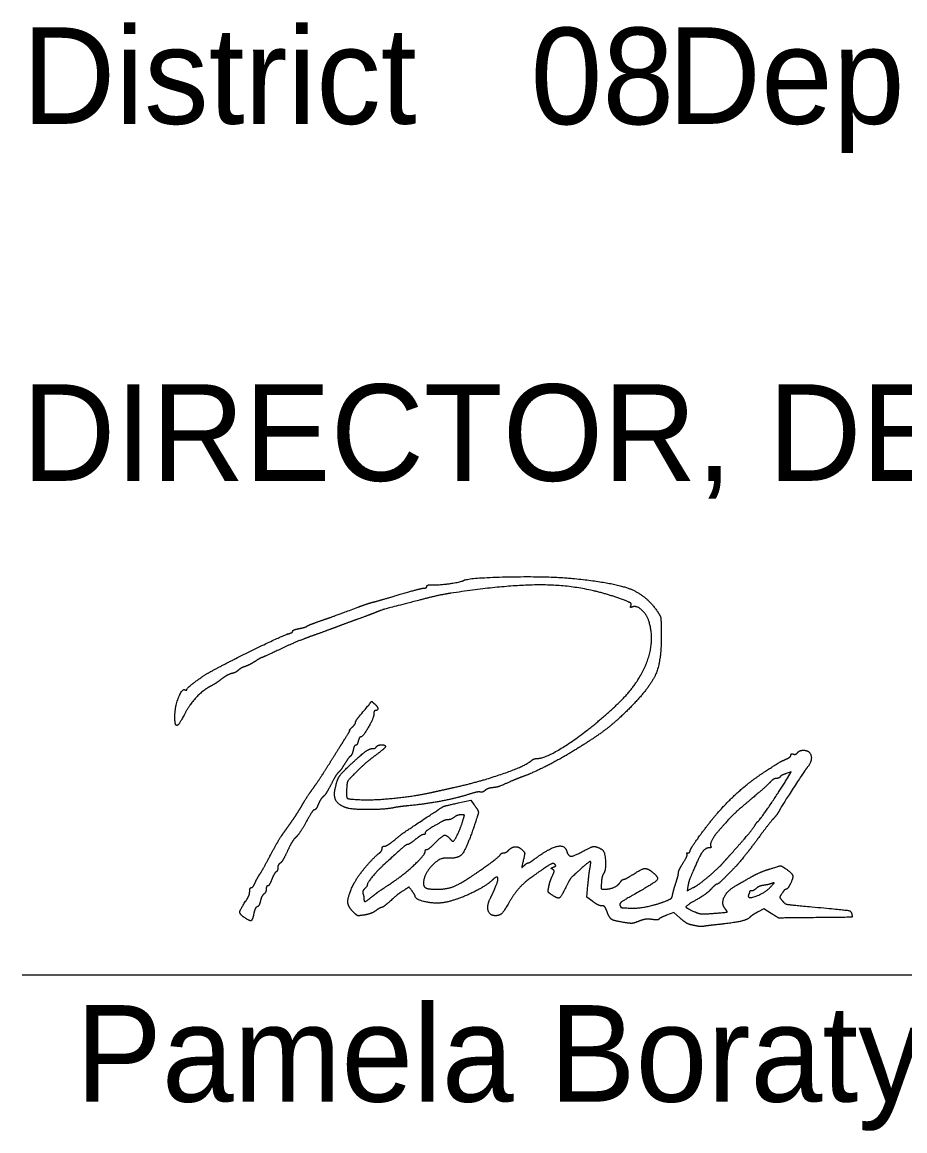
# Model space of a CAD drawing. Extents: x -7.5 to 26.5, y 3.5 to 25.5.
# Drawn here: x 17.043 to 18.323, y 10.747 to 12.355 of the extents above; entities that cross this region are included whole.
import ezdxf

# ---------------------------------------------------------------- set-up
doc = ezdxf.new("R2010")
doc.units = 0
doc.layers.add('SH_Data', color=7, linetype='Continuous')
doc.layers.add('SH_Text', color=7, linetype='Continuous')

msp = doc.modelspace()

# ---------------------------------------------------------------- linework, layer by layer
at = {"layer": 'SH_Data'}
msp.add_line((17.0432, 10.9729), (20.5432, 10.9729), dxfattribs=at)
at = {"layer": 'SH_Text'}
for points in [[(18.1528, 11.2584), (18.1582, 11.2674), (18.1508, 11.2648)], [(17.6755, 11.2223), (17.6935, 11.2263), (17.6981, 11.2201)], [(17.8704, 11.0795), (17.8621, 11.0858), (17.8635, 11.1029)], [(18.0084, 11.1014), (18.0074, 11.095), (18.016, 11.0994)], [(17.9974, 11.0551), (17.9882, 11.0634), (17.9776, 11.0593)], [(18.1292, 11.0621), (18.1186, 11.0689), (18.1102, 11.0644)]]:
    msp.add_lwpolyline(points, dxfattribs=at)
for points in [[(17.6389, 11.5386), (17.6484, 11.5383), (17.6794, 11.5427), (17.6829, 11.5448)], [(17.6829, 11.5448), (17.6896, 11.549), (17.8067, 11.5513), (17.8411, 11.5479)], [(17.8411, 11.5479), (17.9003, 11.5421), (17.9478, 11.5238), (17.9636, 11.5008)], [(17.5931, 11.5253), (17.6092, 11.53), (17.6241, 11.5339), (17.6261, 11.5339)], [(17.6261, 11.5339), (17.6282, 11.5339), (17.6299, 11.535), (17.6299, 11.5364)], [(17.6299, 11.5364), (17.6299, 11.5378), (17.6339, 11.5388), (17.6389, 11.5386)], [(17.9135, 11.5172), (17.863, 11.5362), (17.755, 11.5402), (17.6647, 11.5264)], [(17.5303, 11.5063), (17.5382, 11.5092), (17.549, 11.5128), (17.5543, 11.5141)], [(17.5543, 11.5141), (17.5595, 11.5155), (17.577, 11.5205), (17.5931, 11.5253)], [(17.6203, 11.5167), (17.5693, 11.5035), (17.565, 11.5023), (17.5543, 11.4979)], [(17.6647, 11.5264), (17.6554, 11.525), (17.6354, 11.5206), (17.6203, 11.5167)], [(17.9259, 11.5086), (17.9268, 11.5111), (17.9234, 11.5135), (17.9135, 11.5172)], [(17.4739, 11.4857), (17.4886, 11.4908), (17.495, 11.4931), (17.5303, 11.5063)], [(17.5543, 11.4979), (17.5516, 11.4968), (17.5414, 11.493), (17.5315, 11.4894)], [(17.9283, 11.5065), (17.9257, 11.5055), (17.9249, 11.5061), (17.9259, 11.5086)], [(17.9516, 11.4866), (17.9484, 11.4963), (17.9339, 11.5087), (17.9283, 11.5065)], [(17.9636, 11.5008), (17.9686, 11.4935), (17.9695, 11.4892), (17.9698, 11.4713)], [(17.4559, 11.4785), (17.4572, 11.4795), (17.4653, 11.4827), (17.4739, 11.4857)], [(17.5315, 11.4894), (17.5216, 11.4858), (17.5064, 11.4803), (17.4979, 11.477)], [(17.9061, 11.3654), (17.9371, 11.3948), (17.961, 11.4583), (17.9516, 11.4866)], [(17.3179, 11.4135), (17.3481, 11.4298), (17.4217, 11.4654), (17.4301, 11.4679)], [(17.4301, 11.4679), (17.433, 11.4687), (17.4355, 11.4703), (17.4355, 11.4714)], [(17.4355, 11.4714), (17.4355, 11.4725), (17.4395, 11.4741), (17.4445, 11.4751)], [(17.4445, 11.4751), (17.4494, 11.476), (17.4545, 11.4775), (17.4559, 11.4785)], [(17.4979, 11.477), (17.4893, 11.4738), (17.4731, 11.4679), (17.4619, 11.4639)], [(17.9698, 11.4713), (17.9706, 11.4305), (17.9545, 11.3908), (17.9251, 11.3609)], [(17.4619, 11.4639), (17.4506, 11.4599), (17.4303, 11.4514), (17.4166, 11.4449)], [(17.3908, 11.4331), (17.3902, 11.4331), (17.3857, 11.4306), (17.3808, 11.4275)], [(17.4166, 11.4449), (17.403, 11.4384), (17.3913, 11.4331), (17.3908, 11.4331)], [(17.366, 11.4199), (17.3627, 11.4189), (17.3586, 11.4166), (17.3568, 11.4148)], [(17.3808, 11.4275), (17.3759, 11.4244), (17.3692, 11.421), (17.366, 11.4199)], [(17.2819, 11.3869), (17.2819, 11.389), (17.3073, 11.4078), (17.3179, 11.4135)], [(17.3323, 11.4019), (17.3276, 11.3983), (17.3205, 11.3936), (17.3164, 11.3915)], [(17.3471, 11.41), (17.3436, 11.4091), (17.3369, 11.4055), (17.3323, 11.4019)], [(17.3568, 11.4148), (17.355, 11.413), (17.3506, 11.4108), (17.3471, 11.41)], [(17.2647, 11.349), (17.2648, 11.3622), (17.2754, 11.3888), (17.2796, 11.3862)], [(17.2796, 11.3862), (17.2808, 11.3855), (17.2819, 11.3858), (17.2819, 11.3869)], [(17.3164, 11.3915), (17.306, 11.3862), (17.2861, 11.3654), (17.2798, 11.3532)], [(17.5321, 11.348), (17.5506, 11.3701), (17.5499, 11.3695), (17.554, 11.3661)], [(17.2798, 11.3532), (17.2732, 11.3403), (17.2679, 11.3335), (17.2661, 11.3353)], [(17.5555, 11.3563), (17.5541, 11.3563), (17.5531, 11.354), (17.5531, 11.3512)], [(17.554, 11.3661), (17.5583, 11.3626), (17.5592, 11.3563), (17.5555, 11.3563)], [(17.7894, 11.2867), (17.8035, 11.2867), (17.8716, 11.3326), (17.9061, 11.3654)], [(17.9251, 11.3609), (17.9065, 11.342), (17.8741, 11.3171), (17.8436, 11.2983)], [(17.2661, 11.3353), (17.2653, 11.3361), (17.2646, 11.3423), (17.2647, 11.349)], [(17.5219, 11.3323), (17.5245, 11.3349), (17.5267, 11.3381), (17.5267, 11.3393)], [(17.5267, 11.3393), (17.5267, 11.3405), (17.5291, 11.3444), (17.5321, 11.348)], [(17.5531, 11.3512), (17.5531, 11.3457), (17.5371, 11.3179), (17.5339, 11.3179)], [(17.5091, 11.3118), (17.5146, 11.3205), (17.5187, 11.3275), (17.5181, 11.3275)], [(17.5181, 11.3275), (17.5175, 11.3275), (17.5192, 11.3297), (17.5219, 11.3323)], [(17.4871, 11.2768), (17.4937, 11.2875), (17.5036, 11.3032), (17.5091, 11.3118)], [(17.5268, 11.3059), (17.5256, 11.3059), (17.5239, 11.3027), (17.5231, 11.2987)], [(17.5305, 11.3119), (17.5296, 11.3086), (17.528, 11.3059), (17.5268, 11.3059)], [(17.5339, 11.3179), (17.5329, 11.3179), (17.5313, 11.3152), (17.5305, 11.3119)], [(17.5507, 11.3011), (17.5531, 11.3011), (17.5558, 11.3022), (17.5567, 11.3035)], [(17.5699, 11.3039), (17.5699, 11.3028), (17.5631, 11.2969), (17.5549, 11.2908)], [(17.5567, 11.3035), (17.5585, 11.3064), (17.5699, 11.3067), (17.5699, 11.3039)], [(17.5192, 11.2901), (17.5179, 11.2893), (17.5141, 11.2842), (17.5107, 11.2787)], [(17.5183, 11.2769), (17.5339, 11.2916), (17.5467, 11.3011), (17.5507, 11.3011)], [(17.5231, 11.2987), (17.5222, 11.2948), (17.5204, 11.2909), (17.5192, 11.2901)], [(17.5549, 11.2908), (17.5466, 11.2846), (17.5341, 11.2738), (17.5271, 11.2666)], [(17.8436, 11.2983), (17.8244, 11.2865), (17.7832, 11.2655), (17.7691, 11.2604)], [(18.1501, 11.2854), (18.1543, 11.2873), (18.1579, 11.2901), (18.1579, 11.2916)], [(18.1579, 11.2916), (18.1579, 11.2932), (18.1594, 11.2938), (18.1613, 11.2931)], [(18.1613, 11.2931), (18.1632, 11.2924), (18.166, 11.2934), (18.1676, 11.2953)], [(18.1676, 11.2953), (18.1692, 11.2972), (18.1728, 11.2987), (18.1758, 11.2987)], [(18.1758, 11.2987), (18.1852, 11.2987), (18.1889, 11.2827), (18.1815, 11.2737)], [(17.4653, 11.2439), (17.4707, 11.2514), (17.4805, 11.2662), (17.4871, 11.2768)], [(17.4969, 11.2423), (17.4997, 11.2554), (17.5058, 11.2653), (17.5183, 11.2769)], [(17.5107, 11.2787), (17.5073, 11.2732), (17.5032, 11.2676), (17.5015, 11.2663)], [(17.6695, 11.2448), (17.7064, 11.253), (17.7727, 11.2759), (17.7812, 11.2834)], [(17.7812, 11.2834), (17.7833, 11.2852), (17.787, 11.2867), (17.7894, 11.2867)], [(18.1211, 11.2683), (18.14, 11.2806), (18.1419, 11.2817), (18.1501, 11.2854)], [(18.1815, 11.2737), (18.1774, 11.2687), (18.1446, 11.2182), (18.1414, 11.212)], [(17.5015, 11.2663), (17.4999, 11.2649), (17.4952, 11.2573), (17.4912, 11.2493)], [(17.5271, 11.2666), (17.5163, 11.2557), (17.5142, 11.252), (17.5137, 11.2438)], [(17.7691, 11.2604), (17.7644, 11.2587), (17.7574, 11.2559), (17.7534, 11.2542)], [(18.0265, 11.1758), (18.0487, 11.2066), (18.0937, 11.2506), (18.1211, 11.2683)], [(18.11, 11.1955), (18.1128, 11.1975), (18.141, 11.239), (18.1528, 11.2584)], [(18.1368, 11.2579), (18.1346, 11.2579), (18.1306, 11.2555), (18.1279, 11.2525)], [(18.1421, 11.2601), (18.1414, 11.2589), (18.139, 11.2579), (18.1368, 11.2579)], [(18.1508, 11.2648), (18.1468, 11.2634), (18.1428, 11.2613), (18.1421, 11.2601)], [(17.4486, 11.2183), (17.4524, 11.2249), (17.4599, 11.2364), (17.4653, 11.2439)], [(17.4912, 11.2493), (17.4871, 11.2414), (17.4821, 11.2334), (17.4799, 11.2316)], [(17.5123, 11.2155), (17.5018, 11.2194), (17.4947, 11.2318), (17.4969, 11.2423)], [(17.5137, 11.2438), (17.5128, 11.2303), (17.5168, 11.2275), (17.5375, 11.2269)], [(17.6359, 11.2373), (17.6438, 11.2391), (17.6589, 11.2424), (17.6695, 11.2448)], [(17.714, 11.2402), (17.712, 11.2384), (17.7089, 11.2374), (17.7072, 11.238)], [(17.7248, 11.2443), (17.721, 11.2439), (17.7161, 11.242), (17.714, 11.2402)], [(17.7534, 11.2542), (17.7364, 11.2467), (17.7315, 11.245), (17.7248, 11.2443)], [(18.1279, 11.2525), (18.1253, 11.2495), (18.1128, 11.2385), (18.1003, 11.2279)], [(17.4799, 11.2316), (17.4778, 11.2298), (17.4745, 11.2247), (17.4726, 11.2203)], [(17.5375, 11.2269), (17.5567, 11.2264), (17.6145, 11.2325), (17.6359, 11.2373)], [(17.6892, 11.2343), (17.6728, 11.229), (17.6277, 11.2205), (17.6039, 11.2182)], [(17.7072, 11.238), (17.7056, 11.2386), (17.6975, 11.237), (17.6892, 11.2343)], [(18.1003, 11.2279), (18.0806, 11.2114), (18.0689, 11.2), (18.0523, 11.1811)], [(17.4355, 11.1977), (17.4389, 11.2024), (17.4447, 11.2117), (17.4486, 11.2183)], [(17.4669, 11.2123), (17.4657, 11.2123), (17.4602, 11.2044), (17.4549, 11.1947)], [(17.4726, 11.2203), (17.4708, 11.2159), (17.4682, 11.2123), (17.4669, 11.2123)], [(17.5835, 11.2156), (17.5698, 11.2126), (17.5203, 11.2125), (17.5123, 11.2155)], [(17.6039, 11.2182), (17.5956, 11.2174), (17.5864, 11.2162), (17.5835, 11.2156)], [(17.6215, 11.1959), (17.6531, 11.2169), (17.6545, 11.2176), (17.6755, 11.2223)], [(17.6981, 11.2201), (17.7048, 11.2114), (17.7046, 11.2065), (17.6969, 11.184)], [(18.1414, 11.212), (18.1396, 11.2086), (18.1358, 11.2031), (18.1328, 11.1999)], [(17.422, 11.1785), (17.4261, 11.1843), (17.4322, 11.1929), (17.4355, 11.1977)], [(17.4549, 11.1947), (17.4496, 11.1851), (17.4429, 11.1751), (17.44, 11.1725)], [(17.5822, 11.1679), (17.596, 11.179), (17.594, 11.1776), (17.6215, 11.1959)], [(17.6511, 11.1948), (17.6367, 11.1868), (17.6275, 11.1805), (17.6275, 11.1785)], [(17.6609, 11.1979), (17.6586, 11.1979), (17.6543, 11.1965), (17.6511, 11.1948)], [(17.6696, 11.2014), (17.667, 11.1995), (17.6631, 11.1979), (17.6609, 11.1979)], [(17.6681, 11.1667), (17.6699, 11.1667), (17.6797, 11.1878), (17.6828, 11.1985)], [(17.6795, 11.205), (17.6766, 11.205), (17.6722, 11.2034), (17.6696, 11.2014)], [(17.6828, 11.1985), (17.6845, 11.2043), (17.6841, 11.2051), (17.6795, 11.205)], [(18.1061, 11.1904), (18.1073, 11.1925), (18.109, 11.1948), (18.11, 11.1955)], [(18.1328, 11.1999), (18.1298, 11.1967), (18.1209, 11.1853), (18.113, 11.1747)], [(17.4031, 11.1463), (17.4094, 11.1582), (17.4179, 11.1727), (17.422, 11.1785)], [(17.6248, 11.1763), (17.6233, 11.1763), (17.6181, 11.1731), (17.6131, 11.1691)], [(17.6275, 11.1785), (17.6275, 11.1773), (17.6263, 11.1763), (17.6248, 11.1763)], [(17.6419, 11.1643), (17.652, 11.1744), (17.6585, 11.1763), (17.6635, 11.1703)], [(17.6969, 11.184), (17.6866, 11.1541), (17.6746, 11.141), (17.6587, 11.1423)], [(18.0115, 11.1525), (18.0115, 11.1539), (18.0182, 11.1644), (18.0265, 11.1758)], [(18.0523, 11.1811), (18.0464, 11.1745), (18.0401, 11.1617), (18.0416, 11.1593)], [(18.0748, 11.1526), (18.0901, 11.1697), (18.1036, 11.186), (18.1061, 11.1904)], [(18.113, 11.1747), (18.1051, 11.164), (18.0974, 11.1538), (18.0959, 11.152)], [(17.44, 11.1725), (17.4372, 11.17), (17.4317, 11.1609), (17.4277, 11.1523)], [(17.5651, 11.1561), (17.5651, 11.158), (17.5666, 11.1595), (17.5684, 11.1595)], [(17.6019, 11.1619), (17.6, 11.1619), (17.5915, 11.1546), (17.5663, 11.1314)], [(17.5684, 11.1595), (17.5703, 11.1595), (17.5765, 11.1633), (17.5822, 11.1679)], [(17.6131, 11.1691), (17.6081, 11.1651), (17.603, 11.1619), (17.6019, 11.1619)], [(17.6299, 11.1547), (17.6312, 11.1547), (17.6366, 11.159), (17.6419, 11.1643)], [(17.6635, 11.1703), (17.6651, 11.1683), (17.6672, 11.1667), (17.6681, 11.1667)], [(17.7486, 11.1538), (17.7536, 11.1588), (17.7636, 11.1588), (17.7685, 11.1539)], [(17.7866, 11.1412), (17.8069, 11.1564), (17.8296, 11.162), (17.8326, 11.1526)], [(17.8564, 11.1522), (17.8683, 11.1588), (17.8755, 11.1595), (17.8838, 11.1549)], [(18.0416, 11.1593), (18.0423, 11.1581), (18.0413, 11.1571), (18.0393, 11.1571)], [(17.3877, 11.1187), (17.3899, 11.122), (17.3968, 11.1344), (17.4031, 11.1463)], [(17.4277, 11.1523), (17.4238, 11.1437), (17.4191, 11.1358), (17.4172, 11.1348)], [(17.5216, 11.1), (17.5261, 11.1105), (17.5493, 11.1399), (17.5596, 11.1483)], [(17.5596, 11.1483), (17.5626, 11.1507), (17.5651, 11.1542), (17.5651, 11.1561)], [(17.5814, 11.1081), (17.597, 11.1185), (17.6275, 11.1473), (17.6275, 11.1516)], [(17.6275, 11.1516), (17.6275, 11.1533), (17.6285, 11.1547), (17.6299, 11.1547)], [(17.6935, 11.115), (17.712, 11.1274), (17.7344, 11.1441), (17.7362, 11.1468)], [(17.7362, 11.1468), (17.7372, 11.1485), (17.7396, 11.1499), (17.7414, 11.1499)], [(17.7414, 11.1499), (17.7432, 11.1499), (17.7465, 11.1517), (17.7486, 11.1538)], [(17.7685, 11.1539), (17.7717, 11.1507), (17.7719, 11.1483), (17.7698, 11.1391)], [(17.8326, 11.1526), (17.835, 11.145), (17.8431, 11.1449), (17.8564, 11.1522)], [(17.8838, 11.1549), (17.8881, 11.1525), (17.8898, 11.1245), (17.8859, 11.1193)], [(18.0017, 11.1356), (18.0056, 11.1419), (18.0081, 11.1477), (18.0073, 11.1485)], [(18.0073, 11.1485), (18.0065, 11.1493), (18.0071, 11.1499), (18.0087, 11.1499)], [(18.0087, 11.1499), (18.0102, 11.1499), (18.0115, 11.1511), (18.0115, 11.1525)], [(18.0393, 11.1571), (18.033, 11.1571), (18.0235, 11.1419), (18.0114, 11.1127)], [(18.0592, 11.1351), (18.0623, 11.1386), (18.0693, 11.1465), (18.0748, 11.1526)], [(18.0959, 11.152), (18.0827, 11.1356), (18.0781, 11.1304), (18.0662, 11.1183)], [(17.4139, 11.1283), (17.4139, 11.1258), (17.4127, 11.1231), (17.4114, 11.1222)], [(17.4172, 11.1348), (17.4154, 11.1337), (17.4139, 11.1308), (17.4139, 11.1283)], [(17.5663, 11.1314), (17.5571, 11.123), (17.5435, 11.1059), (17.5435, 11.103)], [(17.6587, 11.1423), (17.6483, 11.1432), (17.6251, 11.1179), (17.6251, 11.1056)], [(17.7698, 11.1391), (17.7674, 11.1289), (17.7676, 11.1284), (17.7714, 11.1318)], [(17.7714, 11.1318), (17.7736, 11.1338), (17.7762, 11.1355), (17.7772, 11.1355)], [(17.7772, 11.1355), (17.7782, 11.1355), (17.7824, 11.1381), (17.7866, 11.1412)], [(17.8153, 11.1334), (17.8135, 11.1352), (17.8076, 11.1325), (17.7951, 11.124)], [(17.8124, 11.1258), (17.8102, 11.1272), (17.8106, 11.1281), (17.8137, 11.1293)], [(17.8137, 11.1293), (17.8166, 11.1304), (17.8171, 11.1316), (17.8153, 11.1334)], [(17.8564, 11.1294), (17.8405, 11.1153), (17.8368, 11.1109), (17.8313, 11.0996)], [(17.8665, 11.1277), (17.8683, 11.1372), (17.8657, 11.1376), (17.8564, 11.1294)], [(17.8635, 11.1029), (17.8643, 11.1122), (17.8657, 11.1234), (17.8665, 11.1277)], [(17.929, 11.1187), (17.942, 11.1269), (17.9496, 11.1277), (17.9573, 11.1217)], [(17.9947, 11.1208), (17.9947, 11.1227), (17.9978, 11.1293), (18.0017, 11.1356)], [(18.0391, 11.1162), (18.047, 11.1231), (18.056, 11.1315), (18.0592, 11.1351)], [(18.0991, 11.1143), (18.107, 11.1188), (18.1202, 11.1245), (18.1284, 11.1269)], [(18.1284, 11.1269), (18.1424, 11.1312), (18.1436, 11.1312), (18.1495, 11.1273)], [(18.1495, 11.1273), (18.1591, 11.121), (18.1615, 11.1136), (18.1568, 11.1046)], [(17.3808, 11.1061), (17.3824, 11.1097), (17.3854, 11.1154), (17.3877, 11.1187)], [(17.4051, 11.1113), (17.403, 11.1061), (17.4004, 11.1019), (17.3992, 11.1019)], [(17.4114, 11.1222), (17.41, 11.1214), (17.4072, 11.1165), (17.4051, 11.1113)], [(17.645, 11.0971), (17.658, 11.0971), (17.6771, 11.1042), (17.6935, 11.115)], [(17.7254, 11.1109), (17.7159, 11.1017), (17.6771, 11.0829), (17.6587, 11.0785)], [(17.7225, 11.0851), (17.7266, 11.0928), (17.7331, 11.1091), (17.7331, 11.1118)], [(17.7331, 11.1118), (17.7331, 11.1149), (17.7291, 11.1144), (17.7254, 11.1109)], [(17.7951, 11.124), (17.7754, 11.1105), (17.7582, 11.0935), (17.7498, 11.0791)], [(17.8067, 11.1003), (17.8074, 11.1045), (17.8097, 11.1115), (17.8117, 11.1159)], [(17.8117, 11.1159), (17.8146, 11.1222), (17.8148, 11.1244), (17.8124, 11.1258)], [(17.8859, 11.1193), (17.8847, 11.1177), (17.8834, 11.112), (17.883, 11.1067)], [(17.9099, 11.1066), (17.9118, 11.1093), (17.9143, 11.1115), (17.9155, 11.1115)], [(17.9155, 11.1115), (17.9167, 11.1115), (17.9228, 11.1147), (17.929, 11.1187)], [(17.9573, 11.1217), (17.967, 11.1141), (17.9601, 11.1062), (17.9285, 11.0884)], [(17.9912, 11.1067), (17.9931, 11.1126), (17.9947, 11.119), (17.9947, 11.1208)], [(18.0114, 11.1127), (18.0103, 11.1101), (18.009, 11.105), (18.0084, 11.1014)], [(18.016, 11.0994), (18.0208, 11.1018), (18.0311, 11.1094), (18.0391, 11.1162)], [(18.0662, 11.1183), (18.0587, 11.1106), (18.0517, 11.1043), (18.0506, 11.1043)], [(18.0795, 11.1032), (18.0823, 11.1048), (18.0911, 11.1097), (18.0991, 11.1143)], [(17.3731, 11.0938), (17.3731, 11.097), (17.3742, 11.0995), (17.3755, 11.0995)], [(17.3755, 11.0995), (17.3769, 11.0995), (17.3792, 11.1025), (17.3808, 11.1061)], [(17.3971, 11.0974), (17.3971, 11.0949), (17.3955, 11.0916), (17.3936, 11.09)], [(17.3992, 11.1019), (17.398, 11.1019), (17.3971, 11.0999), (17.3971, 11.0974)], [(17.5232, 11.0643), (17.5156, 11.0719), (17.515, 11.0848), (17.5216, 11.1)], [(17.5397, 11.0978), (17.5377, 11.0958), (17.5366, 11.0925), (17.5373, 11.0906)], [(17.5435, 11.103), (17.5435, 11.1022), (17.5418, 11.0999), (17.5397, 11.0978)], [(17.5499, 11.0858), (17.5574, 11.0919), (17.5627, 11.0956), (17.5814, 11.1081)], [(17.5972, 11.0959), (17.5889, 11.0905), (17.5864, 11.0885), (17.5752, 11.0785)], [(17.6085, 11.0946), (17.604, 11.1004), (17.6039, 11.1004), (17.5972, 11.0959)], [(17.613, 11.0872), (17.613, 11.088), (17.6109, 11.0913), (17.6085, 11.0946)], [(17.6251, 11.1056), (17.6251, 11.1004), (17.6329, 11.0971), (17.645, 11.0971)], [(17.8113, 11.0888), (17.8063, 11.0921), (17.8055, 11.094), (17.8067, 11.1003)], [(17.8313, 11.0996), (17.8246, 11.0859), (17.8197, 11.0832), (17.8113, 11.0888)], [(17.883, 11.1067), (17.8825, 11.0991), (17.8832, 11.0971), (17.8863, 11.0971)], [(17.8863, 11.0971), (17.8946, 11.0971), (17.9066, 11.102), (17.9099, 11.1066)], [(17.9864, 11.0897), (17.9871, 11.0931), (17.9892, 11.1008), (17.9912, 11.1067)], [(18.0421, 11.0974), (18.0385, 11.0935), (18.0304, 11.0874), (18.0241, 11.0838)], [(18.0506, 11.1043), (18.0495, 11.1043), (18.0457, 11.1012), (18.0421, 11.0974)], [(18.0624, 11.0689), (18.0564, 11.0763), (18.0662, 11.096), (18.0795, 11.1032)], [(18.0964, 11.089), (18.0939, 11.0824), (18.1194, 11.0914), (18.1279, 11.1)], [(18.1007, 11.0947), (18.0991, 11.0947), (18.0979, 11.0943), (18.0979, 11.0937)], [(18.1075, 11.0983), (18.1053, 11.0963), (18.1022, 11.0947), (18.1007, 11.0947)], [(18.1184, 11.1028), (18.1146, 11.1023), (18.1096, 11.1003), (18.1075, 11.0983)], [(18.1303, 11.1056), (18.1276, 11.1046), (18.1223, 11.1033), (18.1184, 11.1028)], [(18.1279, 11.1), (18.1333, 11.1056), (18.1339, 11.1069), (18.1303, 11.1056)], [(18.1509, 11.0971), (18.1497, 11.0971), (18.1471, 11.0945), (18.145, 11.0913)], [(18.1568, 11.1046), (18.1547, 11.1005), (18.152, 11.0971), (18.1509, 11.0971)], [(17.3656, 11.0559), (17.3585, 11.0608), (17.359, 11.0675), (17.3672, 11.0796)], [(17.3672, 11.0796), (17.3704, 11.0843), (17.3731, 11.0907), (17.3731, 11.0938)], [(17.3886, 11.08), (17.3877, 11.076), (17.3856, 11.0722), (17.3839, 11.0716)], [(17.3936, 11.09), (17.3917, 11.0885), (17.3895, 11.0839), (17.3886, 11.08)], [(17.5373, 11.0906), (17.5381, 11.0887), (17.5387, 11.0856), (17.5387, 11.0837)], [(17.5387, 11.0837), (17.5387, 11.0789), (17.5421, 11.0795), (17.5499, 11.0858)], [(17.5752, 11.0785), (17.5704, 11.0742), (17.5656, 11.0707), (17.5645, 11.0707)], [(17.6587, 11.0785), (17.6458, 11.0754), (17.6132, 11.0816), (17.613, 11.0872)], [(17.7292, 11.0587), (17.7208, 11.0587), (17.7168, 11.0745), (17.7225, 11.0851)], [(17.7498, 11.0791), (17.7417, 11.065), (17.7353, 11.0587), (17.7292, 11.0587)], [(17.8834, 11.0731), (17.8808, 11.0731), (17.875, 11.076), (17.8704, 11.0795)], [(17.9285, 11.0884), (17.9153, 11.081), (17.9091, 11.0762), (17.9099, 11.074)], [(17.9239, 11.0697), (17.9344, 11.0691), (17.9605, 11.074), (17.9737, 11.079)], [(17.9737, 11.079), (17.9825, 11.0824), (17.9854, 11.0848), (17.9864, 11.0897)], [(18.0241, 11.0838), (18.0061, 11.0733), (18.0051, 11.0701), (18.0181, 11.0645)], [(18.0979, 11.0937), (18.0979, 11.0932), (18.0972, 11.091), (18.0964, 11.089)], [(18.145, 11.0913), (18.1415, 11.0859), (18.1415, 11.0851), (18.1453, 11.0804)], [(18.1453, 11.0804), (18.149, 11.0758), (18.154, 11.0748), (18.1879, 11.0717)], [(17.3792, 11.0624), (17.3774, 11.0526), (17.3732, 11.0506), (17.3656, 11.0559)], [(17.3839, 11.0716), (17.3821, 11.0709), (17.3801, 11.0668), (17.3792, 11.0624)], [(17.5394, 11.0597), (17.5307, 11.0584), (17.5286, 11.059), (17.5232, 11.0643)], [(17.556, 11.066), (17.5524, 11.0634), (17.5449, 11.0606), (17.5394, 11.0597)], [(17.5645, 11.0707), (17.5634, 11.0707), (17.5595, 11.0686), (17.556, 11.066)], [(17.8909, 11.0653), (17.889, 11.0705), (17.8865, 11.0731), (17.8834, 11.0731)], [(17.9163, 11.0488), (17.9013, 11.0512), (17.8944, 11.0557), (17.8909, 11.0653)], [(17.9099, 11.074), (17.9112, 11.0706), (17.9119, 11.0704), (17.9239, 11.0697)], [(18.0181, 11.0645), (18.0249, 11.0616), (18.0314, 11.061), (18.0449, 11.0621)], [(18.0449, 11.0621), (18.0644, 11.0637), (18.0661, 11.0643), (18.0624, 11.0689)], [(18.1102, 11.0644), (18.1056, 11.0619), (18.1003, 11.0584), (18.0985, 11.0566)], [(18.1759, 11.0557), (18.1401, 11.0553), (18.1398, 11.0554), (18.1292, 11.0621)], [(18.1879, 11.0717), (18.237, 11.0671), (18.2452, 11.0656), (18.2461, 11.0608)], [(17.9374, 11.0507), (17.9304, 11.0479), (17.9248, 11.0474), (17.9163, 11.0488)], [(17.9562, 11.0533), (17.9505, 11.054), (17.9432, 11.053), (17.9374, 11.0507)], [(17.9663, 11.0536), (17.9659, 11.0527), (17.9614, 11.0526), (17.9562, 11.0533)], [(17.9776, 11.0593), (17.9718, 11.0571), (17.9667, 11.0545), (17.9663, 11.0536)], [(18.012, 11.0457), (18.009, 11.0463), (18.0024, 11.0506), (17.9974, 11.0551)], [(18.0985, 11.0566), (18.0947, 11.0528), (18.0733, 11.048), (18.0499, 11.0456)], [(18.2461, 11.0608), (18.247, 11.0566), (18.245, 11.0564), (18.1759, 11.0557)], [(18.0223, 11.0435), (18.0196, 11.0441), (18.015, 11.045), (18.012, 11.0457)], [(18.0307, 11.0432), (18.0287, 11.0428), (18.0249, 11.043), (18.0223, 11.0435)], [(18.0499, 11.0456), (18.0413, 11.0447), (18.0326, 11.0436), (18.0307, 11.0432)]]:
    msp.add_open_spline(points, degree=2, dxfattribs=at)

# ---------------------------------------------------------------- texts
for s, p in [('District       Deputy Director', (17.0432, 12.2071)), ('              08', (17.0521, 12.2066)), ('DIRECTOR, DEPARTMENT OF TRANSPORTATION', (17.0432, 11.6894)), ('Pamela Boratyn', (17.121, 10.789))]:
    msp.add_text(s, height=0.14, dxfattribs=at).set_placement(p)

doc.saveas('drawing.dxf')
